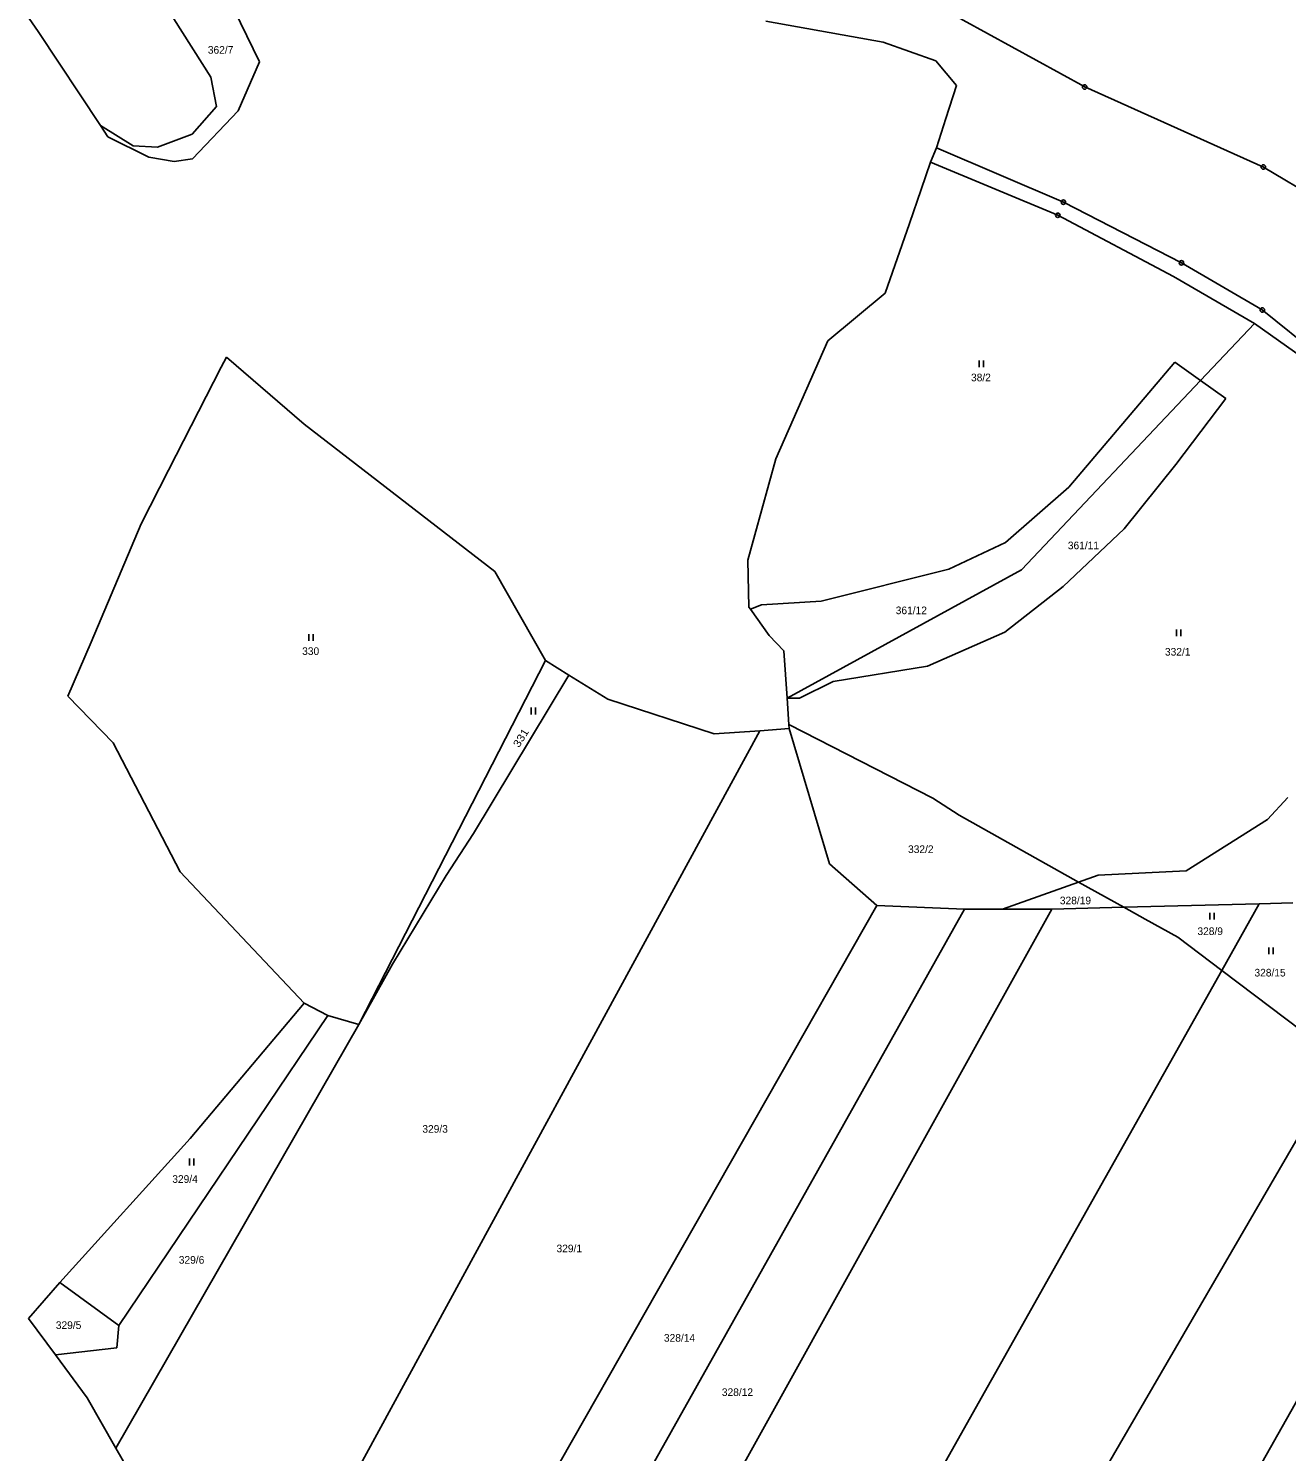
# Model space of a CAD drawing. Extents: x -645290 to -643454, y -1064771 to -1062356.
# Drawn here: x -644946.9 to -644666.5, y -1064149.2 to -1063831.9 of the extents above; entities that cross this region are included whole.
import ezdxf
from ezdxf.enums import TextEntityAlignment as Align

# ---------------------------------------------------------------- set-up
doc = ezdxf.new("R2010")
doc.units = 0
doc.header["$LTSCALE"] = 0.68
for name, color, linetype, lineweight in [('1', 7, 'Continuous', 25), ('3', 7, 'Continuous', 25), ('8', 7, 'Continuous', 25)]:
    doc.layers.add(name, color=color, linetype=linetype, lineweight=lineweight)
doc.layers.add('2', color=7, linetype='Continuous')

msp = doc.modelspace()

# ---------------------------------------------------------------- linework, layer by layer
at = {"layer": '1'}
for p, q in [((-644895.47, -1063839.34), (-644907.94, -1063813.66)), ((-644711.45, -1063844.95), (-644744, -1063827.06)), ((-644946.76, -1063829.65), (-644944.81, -1063832.58)), ((-644906.32, -1063842.75), (-644914.53, -1063829.77)), ((-644782.57, -1063830.25), (-644756.35, -1063834.98)), ((-644944.81, -1063832.58), (-644930.88, -1063853.57)), ((-644756.35, -1063834.98), (-644744.61, -1063839.11)), ((-644900.18, -1063850.29), (-644895.47, -1063839.34)), ((-644744.61, -1063839.11), (-644740.07, -1063844.63)), ((-644905.02, -1063849.29), (-644906.32, -1063842.75)), ((-644740.07, -1063844.63), (-644742.42, -1063851.95)), ((-644671.61, -1063862.81), (-644711.45, -1063844.95)), ((-644910.46, -1063855.49), (-644905.02, -1063849.29)), ((-644910.35, -1063860.99), (-644900.18, -1063850.29)), ((-644742.42, -1063851.95), (-644744.51, -1063858.49)), ((-644930.88, -1063853.57), (-644929.24, -1063856.06)), ((-644930.88, -1063853.57), (-644923.57, -1063858.1)), ((-644929.24, -1063856.06), (-644920.09, -1063860.63)), ((-644918.19, -1063858.37), (-644910.46, -1063855.49)), ((-644923.57, -1063858.1), (-644918.19, -1063858.37)), ((-644744.51, -1063858.49), (-644745.81, -1063861.71)), ((-644716.2, -1063870.65), (-644744.51, -1063858.49)), ((-644920.09, -1063860.63), (-644914.45, -1063861.57)), ((-644914.45, -1063861.57), (-644910.35, -1063860.99)), ((-644745.81, -1063861.71), (-644747.93, -1063867.82)), ((-644717.44, -1063873.56), (-644745.81, -1063861.71)), ((-644653.43, -1063873.64), (-644671.61, -1063862.81)), ((-644747.93, -1063867.82), (-644750.53, -1063875.37)), ((-644689.88, -1063884.18), (-644716.2, -1063870.65)), ((-644691.64, -1063887.19), (-644717.44, -1063873.56)), ((-644750.53, -1063875.37), (-644755.92, -1063890.91)), ((-644671.86, -1063894.68), (-644689.88, -1063884.18)), ((-644673.62, -1063897.69), (-644691.64, -1063887.19)), ((-644755.92, -1063890.91), (-644768.73, -1063901.56)), ((-644656.12, -1063907.37), (-644671.86, -1063894.68)), ((-644685.64, -1063910.4), (-644673.62, -1063897.69)), ((-644673.62, -1063897.69), (-644657.97, -1063908.8)), ((-644768.73, -1063901.56), (-644780.35, -1063927.9)), ((-644902.78, -1063905.17), (-644903.95, -1063907.45)), ((-644885.51, -1063920.16), (-644902.78, -1063905.17)), ((-644691.38, -1063906.29), (-644714.99, -1063934.18)), ((-644685.64, -1063910.4), (-644691.38, -1063906.29)), ((-644903.95, -1063907.45), (-644915.72, -1063930.42)), ((-644725.55, -1063952.63), (-644685.64, -1063910.4)), ((-644679.98, -1063914.45), (-644685.64, -1063910.4)), ((-644679.98, -1063914.45), (-644691.13, -1063929.16)), ((-644842.98, -1063953), (-644885.51, -1063920.16)), ((-644780.35, -1063927.9), (-644786.59, -1063950.47)), ((-644915.72, -1063930.42), (-644921.83, -1063942.34)), ((-644691.13, -1063929.16), (-644702.63, -1063943.5)), ((-644714.99, -1063934.18), (-644729.14, -1063946.53)), ((-644921.83, -1063942.34), (-644932.96, -1063968.78)), ((-644702.63, -1063943.5), (-644716.28, -1063956.37)), ((-644729.14, -1063946.53), (-644741.78, -1063952.51)), ((-644786.59, -1063950.47), (-644786.35, -1063960.92)), ((-644831.68, -1063972.84), (-644842.98, -1063953)), ((-644777.81, -1063981.21), (-644725.55, -1063952.63)), ((-644741.78, -1063952.51), (-644770.24, -1063959.62)), ((-644716.28, -1063956.37), (-644729.28, -1063966.53)), ((-644783.49, -1063960.41), (-644785.97, -1063961.43)), ((-644770.24, -1063959.62), (-644783.49, -1063960.41)), ((-644786.35, -1063960.92), (-644785.97, -1063961.43)), ((-644785.97, -1063961.43), (-644781.77, -1063967.26)), ((-644729.28, -1063966.53), (-644746.52, -1063974.08)), ((-644932.96, -1063968.78), (-644938.16, -1063980.81)), ((-644781.77, -1063967.26), (-644778.54, -1063970.67)), ((-644831.68, -1063972.84), (-644873.3, -1064053.99)), ((-644826.44, -1063976.1), (-644831.68, -1063972.84)), ((-644778.54, -1063970.67), (-644777.81, -1063981.21)), ((-644847.71, -1064011.44), (-644826.44, -1063976.1)), ((-644817.77, -1063981.49), (-644826.44, -1063976.1)), ((-644746.52, -1063974.08), (-644767.52, -1063977.52)), ((-644767.52, -1063977.52), (-644775.04, -1063981.26)), ((-644938.16, -1063980.81), (-644928.05, -1063991.23)), ((-644794.07, -1063989.22), (-644817.77, -1063981.49)), ((-644777.81, -1063981.21), (-644777.41, -1063987.11)), ((-644775.04, -1063981.26), (-644777.81, -1063981.21)), ((-644906.52, -1064213.87), (-644783.89, -1063988.5)), ((-644794.07, -1063989.22), (-644783.89, -1063988.5)), ((-644777.35, -1063988.04), (-644783.89, -1063988.5)), ((-644777.41, -1063987.11), (-644777.35, -1063988.04)), ((-644745.31, -1064003.53), (-644777.41, -1063987.11)), ((-644768.32, -1064018.15), (-644777.35, -1063988.04)), ((-644928.05, -1063991.23), (-644913.09, -1064020)), ((-644739.47, -1064007.35), (-644745.31, -1064003.53)), ((-644666.16, -1064003.4), (-644670.66, -1064008.32)), ((-644712.82, -1064022.25), (-644739.47, -1064007.35)), ((-644670.66, -1064008.32), (-644688.82, -1064019.72)), ((-644847.71, -1064011.44), (-644853.83, -1064020.81)), ((-644913.09, -1064020), (-644885.47, -1064049.23)), ((-644853.83, -1064020.81), (-644865.78, -1064040.58)), ((-644757.8, -1064027.45), (-644768.32, -1064018.15)), ((-644708.47, -1064020.7), (-644712.82, -1064022.25)), ((-644688.82, -1064019.72), (-644708.47, -1064020.7)), ((-644712.82, -1064022.25), (-644729.77, -1064028.29)), ((-644702.76, -1064027.88), (-644712.82, -1064022.25)), ((-644672.56, -1064027.12), (-644702.76, -1064027.88)), ((-644680.91, -1064041.96), (-644672.56, -1064027.12)), ((-644665.04, -1064026.88), (-644672.56, -1064027.12)), ((-644886.54, -1064253.68), (-644757.8, -1064027.45)), ((-644867.77, -1064259.04), (-644738.28, -1064028.29)), ((-644849.89, -1064264.24), (-644718.76, -1064028.29)), ((-644738.28, -1064028.29), (-644757.8, -1064027.45)), ((-644729.77, -1064028.29), (-644738.28, -1064028.29)), ((-644718.76, -1064028.29), (-644729.77, -1064028.29)), ((-644702.76, -1064027.88), (-644718.76, -1064028.29)), ((-644697.99, -1064030.55), (-644702.76, -1064027.88)), ((-644690.67, -1064034.57), (-644697.99, -1064030.55)), ((-644680.91, -1064041.96), (-644690.67, -1064034.57)), ((-644865.78, -1064040.58), (-644873.3, -1064053.99)), ((-644811.6, -1064274.24), (-644680.91, -1064041.96)), ((-644654.09, -1064062.28), (-644680.91, -1064041.96)), ((-644885.47, -1064049.23), (-644910.91, -1064079.47)), ((-644880.2, -1064052), (-644885.47, -1064049.23)), ((-644880.2, -1064052), (-644926.8, -1064121.15)), ((-644873.3, -1064053.99), (-644880.2, -1064052)), ((-644927.45, -1064148.47), (-644873.3, -1064053.99)), ((-644794.48, -1064303.81), (-644654.09, -1064062.28)), ((-644910.91, -1064079.47), (-644939.94, -1064111.53)), ((-644633.09, -1064082.79), (-644728.84, -1064252.56)), ((-644939.94, -1064111.53), (-644946.95, -1064119.55)), ((-644926.8, -1064121.15), (-644939.94, -1064111.53)), ((-644946.95, -1064119.55), (-644940.9, -1064127.71)), ((-644926.8, -1064121.15), (-644927.23, -1064126.1)), ((-644927.23, -1064126.1), (-644940.9, -1064127.71)), ((-644940.9, -1064127.71), (-644933.86, -1064137.23)), ((-644933.86, -1064137.23), (-644927.45, -1064148.47)), ((-644927.45, -1064148.47), (-644913.14, -1064173.54))]:
    msp.add_line(p, q, dxfattribs=at)
at = {"layer": '3'}
for p, q in [((-644735.001, -1063907.45), (-644735.001, -1063905.95)), ((-644734, -1063907.45), (-644734, -1063905.95)), ((-644884.441, -1063968.48), (-644884.441, -1063966.98)), ((-644883.44, -1063968.48), (-644883.44, -1063966.98)), ((-644691.011, -1063967.45), (-644691.011, -1063965.95)), ((-644690.01, -1063967.45), (-644690.01, -1063965.95)), ((-644834.871, -1063984.86), (-644834.871, -1063983.36)), ((-644833.87, -1063984.86), (-644833.87, -1063983.36)), ((-644683.581, -1064030.6), (-644683.581, -1064029.1)), ((-644682.58, -1064030.6), (-644682.58, -1064029.1)), ((-644670.401, -1064038.31), (-644670.401, -1064036.81)), ((-644669.4, -1064038.31), (-644669.4, -1064036.81)), ((-644911.081, -1064085.43), (-644911.081, -1064083.93)), ((-644910.08, -1064085.43), (-644910.08, -1064083.93))]:
    msp.add_line(p, q, dxfattribs=at)
at = {"layer": '8'}
for centre, radius in [((-644711.45, -1063844.9499), 0.5), ((-644711.45, -1063844.9499), 0.0303), ((-644671.61, -1063862.8099), 0.5), ((-644671.61, -1063862.8099), 0.0303), ((-644716.2, -1063870.6499), 0.5), ((-644716.2, -1063870.6499), 0.0303), ((-644717.44, -1063873.5599), 0.5), ((-644717.44, -1063873.5599), 0.0303), ((-644689.88, -1063884.1799), 0.5), ((-644689.88, -1063884.1799), 0.0303), ((-644671.86, -1063894.6799), 0.5), ((-644671.86, -1063894.6799), 0.0303)]:
    msp.add_circle(centre, radius, dxfattribs=at)

# ---------------------------------------------------------------- texts
at = {"layer": '2'}
for s, p in [('362/7', (-644904.11, -1063837.535)), ('38/2', (-644734.589, -1063910.574)), ('361/12', (-644750.11, -1063962.515)), ('330', (-644884.029, -1063971.604)), ('328/9', (-644683.47, -1064034.064)), ('329/4', (-644912.04, -1064089.324)), ('329/5', (-644938.01, -1064121.905))]:
    msp.add_text(s, height=1.7, dxfattribs=at).set_placement(p, align=Align.CENTER)
for s, p in [('361/11', (-644715.21, -1063948.035)), ('332/1', (-644693.56, -1063971.745)), ('332/2', (-644750.84, -1064015.775)), ('328/19', (-644716.99, -1064027.205)), ('328/15', (-644673.6, -1064043.304)), ('329/3', (-644859.13, -1064078.145)), ('329/1', (-644829.21, -1064104.804)), ('329/6', (-644913.43, -1064107.354)), ('328/14', (-644805.27, -1064124.745)), ('328/12', (-644792.35, -1064136.854))]:
    msp.add_text(s, height=1.7, dxfattribs=at).set_placement(p)
at = {"layer": '2', "width": 1.15}
msp.add_text('331', height=1.7, rotation=58, dxfattribs=at).set_placement((-644837.599, -1063992.405))

doc.saveas('drawing.dxf')
